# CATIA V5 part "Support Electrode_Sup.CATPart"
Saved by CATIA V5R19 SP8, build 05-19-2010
Part number: Support Electrode_Sup
Nomenclature: 64
Bounding box of the stored display mesh (mm): x -57.5 to 57.5, y -20 to 20, z -8 to 20
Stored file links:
  C:\Users\rphgr\Desktop\0_Tapis_TC520B_vitesse\Support Electrode_Sup.CATPart
  D:\Documents\1_Travail\1 - ac-limoges.fr\ac-limoges.fr\Emmanuel Maynard - STI2D_Turgot\3 - Supports\Tapis de course TC520B\Tapis de course TC520B_Ca\0_Tapis_TC520B_Conception.CATProduct
  D:\Documents\1_Travail\1 - ac-limoges.fr\ac-limoges.fr\Emmanuel Maynard - STI2D_Turgot\3 - Supports\Tapis de course TC520B\Tapis de course TC520B_Ca\Tapis.CATPart
  D:\Documents\1_Travail\1 - ac-limoges.fr\ac-limoges.fr\Emmanuel Maynard - STI2D_Turgot\3 - Supports\Tapis de course TC520B\Tapis de course TC520B_Ca\Guidon.CATPart
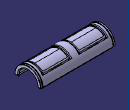
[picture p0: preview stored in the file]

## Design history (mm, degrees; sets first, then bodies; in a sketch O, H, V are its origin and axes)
AxisSystem1: origin (0, 0, 0), X (1, 0, 0), Y (0, 1, 0), Z (0, 0, 1)
Set1
  DatumCurve1
Body1 (main body)
  Sketch1 on ZX plane of AxisSystem1, origin (0, 0, 0), H (0, 0, 1), V (1, 0, 0)
    axis line L1 (0, 0) -> (0, 74.1525)
    point P2 (17, 0)
    line L2 (17, 0) -> (17, 54.5)
    line L3 (17, 54.5) -> (16, 54.5)
    line L4 (16, 54.5) -> (16, 57.5)
    line L5 (16, 57.5) -> (20, 57.5)
    line L6 (20, 57.5) -> (20, 55)
    point P7 (20, 0)
    line L7 (20, 0) -> (17, 0)
    line L8 (19.5, 55) -> (20, 55)
    line L9 (20, 54) -> (19.5, 54)
    line L10 (19.5, 54) -> (19.5, 55)
    line L11 (20, 54) -> (20, 0)
    distance L4 L1 = 16
    distance L4 L2 = 1
    distance L6 L1 = 20
    distance L5 L3 = 3
    distance L5 L7 = 57.5
    distance L8 L5 = 2.5
    distance L8 L9 = 1
    distance L10 L6 = 0.5
    vertical: L1 V, L2 V, L4 V, L6 V, L10 V, L11 V
    coincidence: P2 H, P7 H, L6 L11
    horizontal: L3 H, L5 H, L7 H, L8 H, L9 H
  Shaft1: profile Sketch1, axis Sketch1.L1, angle 90
  Plane1: type Offset, RefPlane XY plane of AxisSystem1, Offset 24
  Sketch2 on Plane1, origin (0, 0, 24), H (1, 0, 0), V (0, 1, 0)
    point P1 (28, -8)
    line L1 (50.5, 0) -> (50.5, -16)
    line L2 (50.5, -16) -> (5.5, -16)
    line L3 (5.5, -16) -> (5.5, 0)
    line L4 (5.5, 0) -> (50.5, 0)
    reference intersected line E1 through (57.5, 0) direction (0, 1) from face of Shaft1 from Sketch1.L5
    reference intersected line E2 through (0, 0) direction (-1, 0) from face of Shaft1
    distance L3 L1 = 45
    distance L4 L2 = 16
    distance L1 E1 = 7
    vertical: L1 V, L3 V
    horizontal: L2 H, L4 H
    equidistance: L1 L3 P1, L2 L4 P1
    coincidence: L4 E2
  Pocket1: profile Sketch2, direction (0, 0, -1), up to face of Shaft1 from Sketch1.L11, offset 1.6
  Sketch3 on xy-plane, origin (0, 0, 0), H (1, 0, 0), V (0, 1, 0)
    point P1 (8.5, 0)
    line L1 (8.5, 0) -> (8.5, -13)
    line L2 (8.5, -13) -> (47.5, -13)
    line L3 (47.5, -13) -> (47.5, 0)
    point P4 (47.5, 0)
    reference intersected line E1 through (50.5, 0) direction (0, 1) from face of Pocket1 from Sketch2.L1
    reference intersected line E2 through (0, -16) direction (1, 0) from face of Pocket1 from Sketch2.L2
    reference intersected line E3 through (5.5, 0) direction (0, -1) from face of Pocket1 from Sketch2.L3
    distance L3 E1 = 3
    distance E2 L2 = 3
    distance L1 E3 = 3
    coincidence: P1 H, P4 H
    vertical: L1 V, L3 V
    horizontal: L2 H
  Pad1: profile Sketch3, direction (0, 0, 1), up to end face of Pocket1, offset 1, opposite side up to face of Shaft1 from Sketch1.L2, thin wall 0, second thickness 1.5
  Fillet1: radius 1, on edge [face of Pad1 | face of Pad1] (x2)
  Fillet2: radius 2, on edge [face of Pad1 | face of Pad1] (x2)
  Sketch4 on Plane1, origin (0, 0, 24), H (1, 0, 0), V (0, 1, 0)
    point P1 (0, -5)
    line L1 (0, -5) -> (4.5, -5)
    arc A1 centre (4.5, 0) radius 5 from (4.5, -5) to (9.5, 0) ccw
    point P3 (4.5, 0)
    point P4 (9.5, 0)
    reference intersected line E1 through (0, 0) direction (0, 1) from face of Shaft1 from Sketch1.L7
    reference intersected line E2 through (0, 0) direction (-1, 0) from face of Shaft2
    reference intersected line E3 through (0, 0) direction (0, 1) from face of Shaft1 from Sketch1.L7
    radius A1 = 5
    distance P4 E3 = 9.5
    coincidence: P1 V, P1 E1, P3 E2
    horizontal: L1 H
    tangency: A1 L1
  Pad2: profile Sketch4, direction (0, 0, -1), up to face of Shaft1 from Sketch1.L2, offset 1, opposite side up to end face of Pocket1, thin wall 0, second thickness 1
  Sketch5 on Plane1, origin (0, 0, 24), H (1, 0, 0), V (0, 1, 0)
    point P1 (49.65, -7.9973)
    line L1 (50.5, 0) -> (50.5, -15.9947)
    line L2 (50.5, -15.9947) -> (48.8, -15.9947)
    line L3 (48.8, -15.9947) -> (48.8, 0)
    line L4 (48.8, 0) -> (50.5, 0)
    reference intersected line E1 (50.5, 16) -> (50.5, -16) from face of Pocket1 from Sketch2.L1
    reference intersected line E2 (5.5, 0) -> (50.5, 0) from face of Pocket1 from Sketch2.L4
    line L5 (5.5, 0) -> (7, 0)
    line L6 (7, 0) -> (7, -16)
    line L7 (7, -16) -> (5.5, -16)
    line L8 (5.5, -16) -> (5.5, 0)
    reference intersected line E3 (5.5, -16) -> (5.5, 0) from face of Pocket1 from Sketch2.L3
    reference intersected line E4 through (7, 0) direction (0, -1) from face of Pad1
    reference intersected line E5 (50.5, -16) -> (5.5, -16) from face of Pocket1 from Sketch2.L2
    reference intersected line E6 through (0, 0) direction (-1, 0) from face of Shaft1
    distance L3 L1 = 1.7
    vertical: L1 V, L3 V, L6 V, L8 V
    horizontal: L2 H, L4 H, L5 H, L7 H
    equidistance: L1 L3 P1, L2 L4 P1
    coincidence: L1 E1, L4 E2, L8 E3, L6 E4, L7 E5, L5 E6
  Pocket2: profile Sketch5, direction (0, 0, -1), up to end face of Pocket1, offset 1
  Sketch6 on face of Shaft1, origin (0, 0, 0), H (-1, 0, 0), V (0, 0, 1)
    line L1 (-51.5, 17) -> (-48.5, 17)
    line L2 (-48.5, 17) -> (-48.5, 16.5)
    line L3 (-48.5, 16.5) -> (-51.5, 16.5)
    line L4 (-51.5, 16.5) -> (-51.5, 17)
    point P5 (-7.75, 17)
    line L5 (-7.75, 17) -> (-4.75, 17)
    line L6 (-4.75, 17) -> (-4.75, 16.5)
    line L7 (-4.75, 16.5) -> (-7.75, 16.5)
    line L8 (-7.75, 16.5) -> (-7.75, 17)
    reference projected line E1 (-54.5, 17) -> (0, 17) from edge [face of Shaft1 from Sketch1.L2 | face of Shaft1]
    reference intersected line E2 (-57.5, 16) -> (-57.5, 20) from face of Shaft1 from Sketch1.L5
    reference intersected line E3 (-5.5, 24) -> (-5.5, 18.4) from face of Pocket1
    distance L4 L2 = 3
    distance L2 E2 = 9
    distance L3 L1 = 0.5
    distance L8 L6 = 3
    distance E3 L6 = 0.75
    horizontal: L1 H, L3 H, L5 H, L7 H
    vertical: L2 V, L4 V, L6 V, L8 V
    coincidence: P5 L1, L1 E1, L7 L3
  Shaft2: profile Sketch6, axis axis of face of Shaft1 from Sketch1.L2, angle 75
  Sketch7 on XY plane of AxisSystem1, origin (0, 0, 0), H (1, 0, 0), V (0, 1, 0)
    line L1 (46.5, -16) -> (36.5, -16)
    line L2 (36.5, -16) -> (36.5, -14.5)
    line L3 (36.5, -14.5) -> (46.5, -14.5)
    line L4 (46.5, -14.5) -> (46.5, -16)
    point P5 (19.5, -14.5)
    line L5 (19.5, -14.5) -> (9.5, -14.5)
    line L6 (9.5, -14.5) -> (9.5, -16)
    line L7 (9.5, -16) -> (19.5, -16)
    line L8 (19.5, -16) -> (19.5, -14.5)
    point P7 (9.5, -16)
    line L9 (5.5, 0) -> (7, 0)
    line L10 (7, 0) -> (7, -4)
    line L11 (7, -4) -> (5.5, -4)
    line L12 (5.5, -4) -> (5.5, 0)
    reference intersected line E1 through (0, -16) direction (1, 0) from face of Pocket1 from Sketch2.L2
    reference intersected line E2 through (5.5, 0) direction (0, -1) from face of Pocket1 from Sketch2.L3
    reference intersected line E3 through (0, 0) direction (-1, 0) from face of Shaft1
    reference intersected line E4 through (0, -14.5) direction (1, 0) from face of Pad1
    reference intersected line E5 through (50.5, 0) direction (0, 1) from face of Pocket1
    reference intersected line E6 through (7, 0) direction (0, -1) from face of Pad1
    distance L11 L9 = 4
    distance L6 L8 = 10
    distance L2 L4 = 10
    distance L2 L8 = 17
    distance L4 E5 = 4
    horizontal: L1 H, L3 H, L5 H, L7 H, L9 H, L11 H
    vertical: L2 V, L4 V, L6 V, L8 V, L10 V, L12 V
    coincidence: P5 L3, P7 L1, L7 E1, L12 E2, L9 E3, L5 E4, L10 E6
  Pocket3: profile Sketch7, direction (0, 0, -1), through (limit type 3)
  Sketch8 on XY plane of AxisSystem1, origin (0, 0, 0), H (1, 0, 0), V (0, 1, 0)
    point P1 (9.5, -16)
    line L1 (9.5, -16) -> (9.5, -11)
    line L2 (9.5, -11) -> (11.5, -11)
    line L3 (11.5, -11) -> (11.5, -6)
    line L4 (11.5, -6) -> (17.5, -6)
    line L5 (17.5, -6) -> (17.5, -11)
    point P6 (17.5, -11)
    line L6 (17.5, -11) -> (19.5, -11)
    line L7 (19.5, -11) -> (19.5, -16)
    point P8 (19.5, -16)
    reference intersected line E1 through (19.5, 0) direction (0, -1) from face of Pocket3 from Sketch7.L8
    reference intersected line E2 through (9.5, 0) direction (0, 1) from face of Pocket3 from Sketch7.L6
    reference intersected line E3 through (0, -16) direction (1, 0) from face of Pocket3
    reference intersected line E4 through (0, -16) direction (1, 0) from face of Pocket3
    length L1 = 5
    distance L2 L4 = 5
    distance L3 L5 = 6
    distance L3 L1 = 2
    vertical: L1 V, L3 V, L5 V, L7 V
    horizontal: L2 H, L4 H, L6 H
    coincidence: P6 L2, L7 E1, L1 E2, P1 E3, P8 E4
  Pad3: profile Sketch8, direction (0, 0, 1), up to end face of Pocket1, offset -0.5, opposite side up to face of Shaft1 from Sketch1.L2, offset 0.5, thin wall 0, second thickness 1
  RectPattern1: of Pad3, direction 1 instances 2, spacing 27, along edge [face of Shaft1 | face of Shaft1 from Sketch1.L2] reversed
  Sketch9 on face of Shaft1, origin (0, 0, 0), H (1, 0, 0), V (0, -1, 0)
    projected line E1 (54.5, 16) -> (54.5, 17) from edge [face of Shaft1 | face of Shaft1 from Sketch1.L3]
    projected line E2 (54.5, 17) -> (0, 17) from edge [face of Shaft1 | face of Shaft1 from Sketch1.L2]
  Pad4: profile Sketch9, direction (0, 0, -1), length 2.4, thin wall 0, second thickness 1.3
  Fillet3: radius 0.5, on edge [face of Pad4 | face of Pad4]; edge [face of Shaft1 from Sketch1.L6 | face of Shaft1 from Sketch1.L5]
  Mirror1: of the body so far, about face of Shaft2
  Sketch10 on xy-plane, origin (0, 0, 0), H (1, 0, 0), V (0, 1, 0)
    circle A1 centre (32, 0) radius 3.25
    point P1 (32, 0)
    reference projected point E1 (32, 0) from edge of DatumCurve1
    radius A1 = 3.25
    coincidence: P1 H
    concentricity: A1 E1
  Pad5: profile Sketch10, direction (0, 0, 1), up to face of Shaft1 from Sketch1.L2, opposite side length 8
  Draft1: PullDir start face of Pad5, Angle 2, SupportToDraft face of Pad5 from Sketch10.A1, Neutral start face of Pad5
  Mirror2: of the body so far, about face of Pad4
